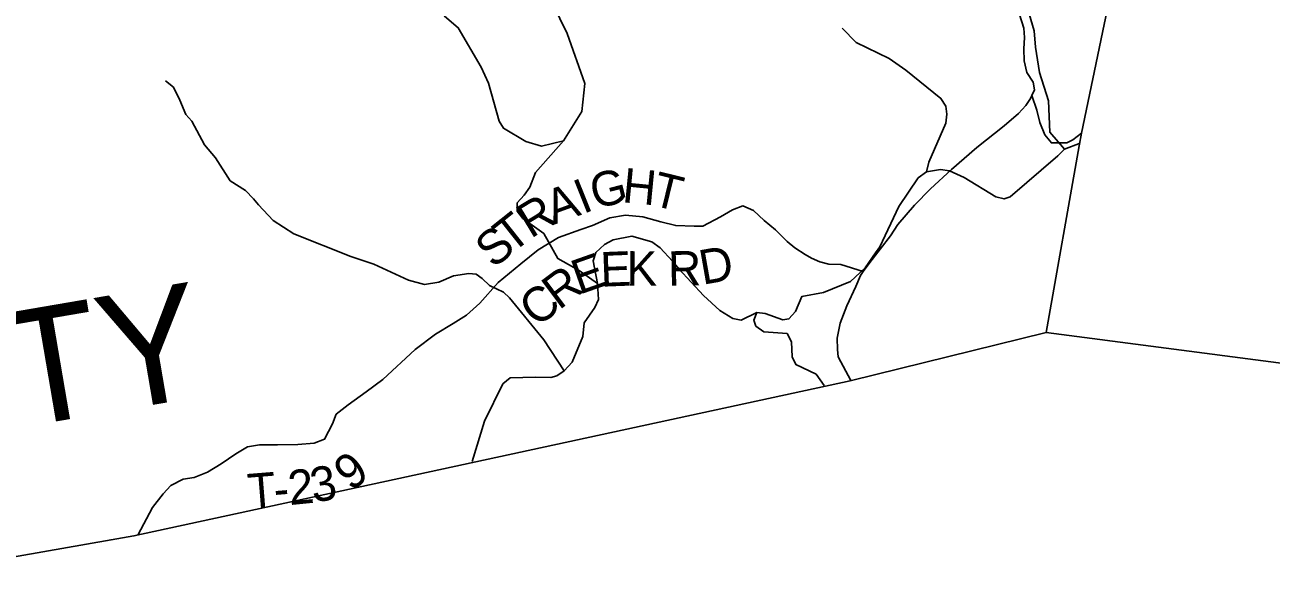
# Model space of a CAD drawing. Extents: x 0 to 34, y 0 to 22.
# Drawn here: x 26.267 to 28.315, y 14.865 to 15.772 of the extents above; entities that cross this region are included whole.
import ezdxf

# ---------------------------------------------------------------- set-up
doc = ezdxf.new("R2010")
doc.units = 0
for name, color, linetype in [('GM_X_Adjacent_County', 7, 'Continuous'), ('GM_X_Adjacent_County_Text', 7, 'Continuous'), ('GM_X_County', 7, 'Continuous'), ('GM_X_Major_River', 7, 'Continuous'), ('GM_X_Minor_River', 7, 'Continuous'), ('GM_X_State_Route', 7, 'Continuous'), ('GM_X_Township', 7, 'Continuous'), ('GM_X_Township_Road', 7, 'Continuous'), ('GM_X_Township_Road_Text', 7, 'Continuous')]:
    doc.layers.add(name, color=color, linetype=linetype)

msp = doc.modelspace()

# ---------------------------------------------------------------- linework, layer by layer
at = {"layer": 'GM_X_Adjacent_County'}
for points in [[(29.025, 20.9), (28.9523, 20.4546), (28.8745, 20.061), (28.5665, 18.3656), (28.4154, 17.5565), (28.2182, 16.6548), (28.1843, 16.461), (28.0039, 15.594), (27.9998, 15.5735), (27.9456, 15.2665), (28.3274, 15.217), (28.5345, 15.206), (29.5448, 15.1357), (29.7209, 15.1252), (30.2392, 15.0941), (30.8167, 15.0595)], [(30.8167, 15.0595), (30.2392, 15.0941), (29.7209, 15.1252), (29.5448, 15.1357), (28.5345, 15.206), (28.3274, 15.217), (27.9456, 15.2665), (27.6234, 15.1875), (26.4461, 14.9325), (26.4085, 14.9262), (24.8262, 14.6485), (24.6978, 14.628), (24.0167, 14.5214)]]:
    msp.add_lwpolyline(points, dxfattribs=at)
at = {"layer": 'GM_X_County'}
msp.add_lwpolyline([(24.0167, 14.5214), (24.6978, 14.628), (24.8262, 14.6485), (26.4085, 14.9262), (26.4461, 14.9325), (27.6234, 15.1875), (27.9456, 15.2665), (27.9998, 15.5735), (28.0039, 15.594), (28.1843, 16.461), (28.2182, 16.6548), (28.4154, 17.5565), (28.5665, 18.3656), (28.8745, 20.061), (28.9523, 20.4546), (29.025, 20.9)], dxfattribs=at)
at = {"layer": 'GM_X_Major_River'}
for points in [[(27.2083, 15.347), (27.1781, 15.3687), (27.1427, 15.388), (27.1197, 15.4295), (27.0855, 15.4541), (27.0761, 15.4659), (27.0759, 15.4796), (27.0873, 15.492), (27.0966, 15.5055), (27.1062, 15.5293), (27.1522, 15.5815), (27.1821, 15.6297), (27.1871, 15.6759), (27.1584, 15.758), (27.1343, 15.8071)], [(27.0021, 15.0545), (27.0224, 15.1211), (27.0523, 15.1821), (27.0646, 15.1922), (27.1063, 15.1932), (27.1316, 15.1928), (27.1412, 15.1954), (27.1534, 15.2036), (27.1664, 15.2178), (27.1837, 15.26), (27.1859, 15.2828), (27.2036, 15.3076), (27.2095, 15.3208), (27.2083, 15.347)]]:
    msp.add_lwpolyline(points, dxfattribs=at)
at = {"layer": 'GM_X_Minor_River'}
for points in [[(27.9757, 15.5679), (27.9514, 15.5955), (27.9494, 15.6475), (27.9345, 15.6936), (27.9282, 15.7354), (27.9256, 15.7624), (27.9147, 15.7993), (27.9122, 15.8414), (27.9266, 15.9007), (27.928, 15.9242), (27.9183, 15.9881), (27.9194, 16.0165), (27.932, 16.0558), (27.9613, 16.096), (27.9755, 16.1068), (27.9888, 16.1093), (28.0024, 16.1091), (28.0127, 16.1124), (28.0522, 16.1524), (28.0884, 16.169), (28.1256, 16.1932)], [(27.1522, 15.5815), (27.1161, 15.5728), (27.0901, 15.5806), (27.0536, 15.6022), (27.0462, 15.614), (27.0286, 15.6763), (27.0168, 15.7026), (26.9792, 15.7674), (26.9563, 15.7862), (26.9308, 15.8137), (26.9188, 15.8221), (26.8932, 15.8326), (26.8771, 15.8533), (26.8643, 15.861), (26.8386, 15.8635), (26.8119, 15.8725), (26.7864, 15.8667), (26.7484, 15.8807)], [(27.749, 15.5307), (27.7526, 15.5466), (27.7808, 15.6107), (27.7825, 15.6254), (27.7804, 15.6383), (27.7726, 15.6513), (27.7148, 15.6976), (27.6874, 15.7165), (27.6332, 15.743), (27.6104, 15.7665)], [(27.1534, 15.2036), (27.1196, 15.2544), (27.0633, 15.3238), (27.0535, 15.333), (27.0306, 15.3439), (27.0182, 15.3555), (27.0085, 15.3624), (26.9967, 15.3637), (26.9713, 15.3599), (26.9473, 15.3492), (26.9234, 15.3453), (26.8973, 15.3529), (26.8405, 15.379), (26.8024, 15.3913), (26.7089, 15.4289), (26.6747, 15.4506), (26.6508, 15.4763), (26.6426, 15.4863), (26.6295, 15.5001), (26.6043, 15.516), (26.5802, 15.5538), (26.5623, 15.5749), (26.5412, 15.6139), (26.5311, 15.6246), (26.5216, 15.6482), (26.5112, 15.6696), (26.4981, 15.68)], [(27.2083, 15.347), (27.2008, 15.3846), (27.2052, 15.3982), (27.2197, 15.4113), (27.2338, 15.4187), (27.2646, 15.4251), (27.2971, 15.4156), (27.311, 15.4055), (27.3311, 15.384), (27.342, 15.3714), (27.3823, 15.3272), (27.4093, 15.303), (27.4307, 15.2895), (27.4443, 15.287), (27.4698, 15.2996), (27.4838, 15.2979), (27.5129, 15.2876), (27.5227, 15.289), (27.5335, 15.3014), (27.5441, 15.3259), (27.5798, 15.3323), (27.6239, 15.3507), (27.6481, 15.3731), (27.6651, 15.3975), (27.6724, 15.4073), (27.7036, 15.4736), (27.7353, 15.5206), (27.749, 15.5307), (27.7718, 15.5342), (27.7866, 15.5325), (27.811, 15.5212), (27.8629, 15.4894), (27.8765, 15.4862), (27.8864, 15.4898), (27.9649, 15.5571), (27.9757, 15.5679), (28.0013, 15.5779)], [(27.4698, 15.2996), (27.4651, 15.2867), (27.4684, 15.2772), (27.4815, 15.2676), (27.5198, 15.2648), (27.5268, 15.2514), (27.528, 15.2268), (27.5339, 15.2142), (27.5674, 15.1982), (27.5804, 15.1794)]]:
    msp.add_lwpolyline(points, dxfattribs=at)
at = {"layer": 'GM_X_State_Route'}
msp.add_lwpolyline([(27.6247, 15.1878), (27.6035, 15.2268), (27.6025, 15.239), (27.6019, 15.2576), (27.6072, 15.2822), (27.6181, 15.3105), (27.6329, 15.3423), (27.6403, 15.3604), (27.6448, 15.3666), (27.6557, 15.3815), (27.6899, 15.4255), (27.7015, 15.4443), (27.7292, 15.4758), (27.7552, 15.5025), (27.7901, 15.5347), (27.8318, 15.5706), (27.8766, 15.6062), (27.9003, 15.6264), (27.9122, 15.6395), (27.9199, 15.6512), (27.9221, 15.656), (27.9265, 15.6655), (27.924, 15.6781), (27.9136, 15.6938), (27.9093, 15.7132), (27.9091, 15.7329), (27.9101, 15.7515), (27.9088, 15.7667), (27.9018, 15.7892)], dxfattribs=at)
at = {"layer": 'GM_X_Township'}
msp.add_lwpolyline([(24.0167, 14.5214), (24.6978, 14.628), (24.8262, 14.6485), (26.4085, 14.9262), (26.4461, 14.9325), (27.6234, 15.1875), (27.9456, 15.2665), (27.9998, 15.5735), (28.0039, 15.594), (28.1843, 16.461), (28.2182, 16.6548), (28.4154, 17.5565), (28.5665, 18.3656), (28.8745, 20.061), (28.9523, 20.4546), (29.025, 20.9)], dxfattribs=at)
at = {"layer": 'GM_X_Township_Road'}
for points in [[(27.9221, 15.656), (27.93, 15.6318), (27.9351, 15.6118), (27.9436, 15.5913), (27.9543, 15.5781), (27.9797, 15.5785), (27.9894, 15.5834), (28.0039, 15.594)], [(26.4526, 14.9335), (26.4766, 14.979), (26.4939, 15.0019), (26.5067, 15.0152), (26.5267, 15.026), (26.5453, 15.0287), (26.5672, 15.0372), (26.5895, 15.051), (26.6133, 15.0675), (26.6329, 15.079), (26.6526, 15.0822), (26.6818, 15.082), (26.7156, 15.0829), (26.7421, 15.0846), (26.7595, 15.0915), (26.7726, 15.1167), (26.7786, 15.1323), (26.7982, 15.1479), (26.828, 15.1694), (26.8552, 15.1893), (26.9083, 15.2386), (26.9415, 15.2642), (26.9706, 15.2814), (26.9925, 15.2952), (27.0144, 15.3147), (27.0449, 15.3487), (27.0822, 15.3793), (27.1105, 15.4026), (27.1441, 15.4229), (27.1808, 15.436), (27.1998, 15.4422), (27.2285, 15.4549), (27.2543, 15.4592), (27.2823, 15.4568), (27.3123, 15.4482), (27.3367, 15.4423), (27.367, 15.4413), (27.3814, 15.4414), (27.4101, 15.4564), (27.4298, 15.4679), (27.4472, 15.4745), (27.4647, 15.467), (27.4818, 15.4508), (27.5005, 15.4353), (27.52, 15.4161), (27.5322, 15.4055), (27.5493, 15.3946), (27.56, 15.3886), (27.5737, 15.3827), (27.5885, 15.3789), (27.6078, 15.3783), (27.6448, 15.3666)]]:
    msp.add_lwpolyline(points, dxfattribs=at)

# ---------------------------------------------------------------- texts
at = {"layer": 'GM_X_Adjacent_County_Text'}
msp.add_text('HIGHLAND COUNTY', height=0.189394, rotation=9.7068, dxfattribs=at).set_placement((24.1589, 14.7512))
at = {"layer": 'GM_X_Township_Road_Text'}
for s, rotation, p in [('G', 14.1343, (27.204, 15.469)), ('H', 354.4435, (27.2474, 15.4808)), ('T', 346.1997, (27.295, 15.4764)), ('A', 19.9327, (27.1354, 15.4432)), ('I', 21.8598, (27.1843, 15.4609)), ('R', 31.283, (27.0982, 15.4202)), ('T', 38.5681, (27.0665, 15.3948)), ('S', 39.6942, (27.0372, 15.3705)), ('D', 10.0172, (27.3807, 15.3449)), ('E', 19.4379, (27.178, 15.3285)), ('E', 2.2377, (27.2137, 15.3418)), ('K', 359.8616, (27.2555, 15.3435)), ('R', 0.8272, (27.3242, 15.3433)), ('R', 36.8059, (27.1447, 15.3027)), ('C', 39.2334, (27.109, 15.2736)), ('9', 37.2042, (26.8027, 15.0046)), ('T', 4.5818, (26.6352, 14.9775)), ('2', 5.7138, (26.702, 14.983)), ('3', 9.5822, (26.741, 14.987)), ('-', 4.7928, (26.6778, 14.9809))]:
    msp.add_text(s, height=0.0568, rotation=rotation, dxfattribs=at).set_placement(p)

doc.saveas('drawing.dxf')
